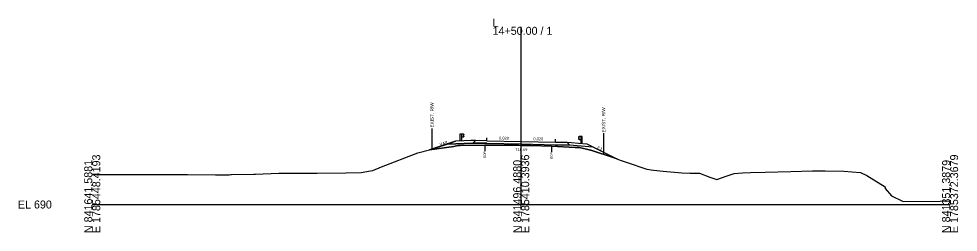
# Model space of a CAD drawing. Extents: x -26 to 5203, y -10 to 9576.
# Drawn here: x -25.7 to 302.8, y 4490.3 to 4565 of the extents above; entities that cross this region are included whole.
import ezdxf

# ---------------------------------------------------------------- set-up
doc = ezdxf.new("R2010")
doc.units = 0
for name, color, linetype in [('Exist Cross Section Cell', 7, 'Continuous'), ('Exist XS Center Line Elevation Label', 7, 'Continuous'), ('Exist XS Ground Line', 7, 'Continuous'), ('Old_Level_10', 7, 'Continuous'), ('Prop XS Earthwork Shape', 7, 'Continuous'), ('Prop XS EOT Tick Mark', 7, 'Continuous'), ('Prop XS Finish Grade', 7, 'Continuous'), ('Prop XS Finish Grade Earthwork', 7, 'Continuous'), ('Prop XS Finish Grade Paved Shoulder', 7, 'Continuous'), ('Prop XS Finish Grade Pavement', 7, 'Continuous'), ('Prop XS Guardrail', 7, 'Continuous'), ('Prop XS Hydro Fill Slope Data', 7, 'Continuous'), ('Prop XS Pvmt Edge Slope', 7, 'Continuous'), ('Prop XS SE Text', 7, 'Continuous'), ('Prop XS Side Slope Text', 7, 'Continuous'), ('Prop XS Subgrade Earthwork', 7, 'Continuous')]:
    doc.layers.add(name, color=color, linetype=linetype)

msp = doc.modelspace()

# ---------------------------------------------------------------- linework, layer by layer
at = {"layer": 'Exist Cross Section Cell'}
for p, q in [((150, 4500), (150, 4562.16)), ((0, 4500), (150, 4500)), ((150, 4500), (300, 4500))]:
    msp.add_line(p, q, dxfattribs=at)
at = {"layer": 'Exist XS Ground Line'}
msp.add_lwpolyline([(0, 4510.46), (3.11, 4510.46), (7.54, 4510.46), (18.23, 4510.45), (31.95, 4510.44), (33.34, 4510.44), (43.12, 4510.43), (47.87, 4510.43), (48.41, 4510.44), (48.74, 4510.44), (56.55, 4510.61), (56.95, 4510.62), (57.13, 4510.63), (65.23, 4510.94), (75.36, 4510.97), (78.69, 4511.01), (88.71, 4511.06), (94.05, 4511.18), (97.35, 4511.79), (98.18, 4511.95), (101.14, 4513.17), (113.91, 4518.04), (117.96, 4519.11), (126.45, 4520.32), (127.84, 4520.6), (128.13, 4520.63), (128.65, 4520.63), (137.27, 4520.71), (144.75, 4520.71), (149.05, 4520.72), (150, 4520.69), (153.52, 4520.59), (160.59, 4520.41), (168.85, 4519.96), (170.4, 4519.9), (174.3, 4518.97), (174.31, 4518.97), (182.89, 4516.16), (184.65, 4515.52), (187.01, 4514.72), (193.98, 4512.41), (196.24, 4512.04), (199.62, 4511.66), (206.13, 4511.13), (208.98, 4510.95), (212.34, 4510.96), (216, 4509.55), (218.45, 4508.75), (221.74, 4509.91), (224.46, 4510.83), (227.43, 4511.07), (230.19, 4511.14), (235.33, 4511.28), (244.3, 4511.53), (251.89, 4511.73), (256.32, 4511.83), (262.83, 4511.7), (268.7, 4511.16), (270.86, 4510.11), (277.3, 4506.15), (277.33, 4505.63), (279.46, 4503.07), (279.78, 4502.93), (283.15, 4501.29), (283.6, 4501.03), (296.55, 4501.19), (300, 4501.3)], dxfattribs=at)
at = {"layer": 'Old_Level_10'}
for p, q in [((118.8, 4526.63), (118.8, 4519.23)), ((178.8, 4524.9), (178.8, 4517.5)), ((137.27, 4520.71), (137.27, 4518.66)), ((160.59, 4520.41), (160.59, 4518.36))]:
    msp.add_line(p, q, dxfattribs=at)
at = {"layer": 'Prop XS Earthwork Shape'}
msp.add_lwpolyline([(137.98, 4521.41), (149.98, 4521.17), (161.98, 4520.93), (166.94, 4520.83), (175.05, 4520.18), (183.63, 4515.89), (182.89, 4516.16), (174.31, 4518.97), (174.3, 4518.97), (170.4, 4519.9), (168.85, 4519.96), (160.59, 4520.41), (153.52, 4520.59), (150, 4520.69), (149.05, 4520.72), (144.75, 4520.71), (137.27, 4520.71), (128.65, 4520.63), (128.13, 4520.63), (127.84, 4520.6), (126.45, 4520.32), (117.96, 4519.11), (124.07, 4521.15), (133.1, 4521.51)], close=True, dxfattribs=at)
at = {"layer": 'Prop XS EOT Tick Mark'}
for p, q in [((138, 4522.33), (138, 4523.33)), ((162, 4521.85), (162, 4522.85))]:
    msp.add_line(p, q, dxfattribs=at)
at = {"layer": 'Prop XS Finish Grade'}
for p, q in [((124.07, 4521.15), (127, 4522.13)), ((130, 4522.25), (127, 4522.13)), ((132.43, 4522.34), (130, 4522.25)), ((134, 4522.41), (132.43, 4522.34)), ((166, 4521.77), (167.57, 4521.64)), ((167.57, 4521.64), (170, 4521.45)), ((170, 4521.45), (173, 4521.21)), ((173, 4521.21), (175.05, 4520.18))]:
    msp.add_line(p, q, dxfattribs=at)
at = {"layer": 'Prop XS Finish Grade Earthwork'}
for p, q in [((124.07, 4521.15), (117.96, 4519.11)), ((175.05, 4520.18), (183.63, 4515.89))]:
    msp.add_line(p, q, dxfattribs=at)
at = {"layer": 'Prop XS Finish Grade Paved Shoulder'}
for p, q in [((138, 4522.33), (134, 4522.41)), ((162, 4521.85), (166, 4521.77))]:
    msp.add_line(p, q, dxfattribs=at)
at = {"layer": 'Prop XS Finish Grade Pavement'}
for p, q in [((138, 4522.33), (150, 4522.09)), ((150, 4522.09), (162, 4521.85))]:
    msp.add_line(p, q, dxfattribs=at)
at = {"layer": 'Prop XS Guardrail'}
for p, q in [((128.68, 4524.69), (129.18, 4524.69)), ((128.68, 4522.19), (128.68, 4524.69)), ((129.18, 4524.69), (129.68, 4524.69)), ((129.18, 4524.69), (129.18, 4522.19)), ((129.68, 4524.69), (129.97, 4524.49)), ((129.97, 4524.37), (129.68, 4524.17)), ((129.68, 4524.17), (129.68, 4524.08)), ((129.68, 4524.08), (129.97, 4523.88)), ((129.97, 4524.49), (130, 4524.43)), ((130, 4524.43), (129.97, 4524.37)), ((129.68, 4523.56), (129.18, 4523.56)), ((129.97, 4523.76), (129.68, 4523.56)), ((129.97, 4523.88), (130, 4523.82)), ((130, 4523.82), (129.97, 4523.76)), ((170.03, 4523.64), (170, 4523.58)), ((170, 4523.58), (170.03, 4523.52)), ((170.03, 4523.03), (170, 4522.97)), ((170, 4522.97), (170.03, 4522.91)), ((170.32, 4523.84), (170.03, 4523.64)), ((170.03, 4523.52), (170.32, 4523.32)), ((170.32, 4523.23), (170.03, 4523.03)), ((170.03, 4522.91), (170.32, 4522.71)), ((170.82, 4523.84), (170.32, 4523.84)), ((170.32, 4523.32), (170.32, 4523.23)), ((170.32, 4522.71), (170.82, 4522.71)), ((171.32, 4523.84), (170.82, 4523.84)), ((170.82, 4523.84), (170.82, 4521.34)), ((171.32, 4521.34), (171.32, 4523.84))]:
    msp.add_line(p, q, dxfattribs=at)
at = {"layer": 'Prop XS Hydro Fill Slope Data'}
for p, q in [((127, 4522.13), (117.96, 4519.11)), ((173, 4521.21), (183.63, 4515.89))]:
    msp.add_line(p, q, dxfattribs=at)
at = {"layer": 'Prop XS Pvmt Edge Slope'}
for p, q in [((134, 4522.41), (133.1, 4521.51)), ((166, 4521.77), (166.94, 4520.83))]:
    msp.add_line(p, q, dxfattribs=at)
at = {"layer": 'Prop XS Subgrade Earthwork'}
for p, q in [((133.1, 4521.51), (124.07, 4521.15)), ((137.98, 4521.41), (133.1, 4521.51)), ((137.98, 4521.41), (149.98, 4521.17)), ((149.98, 4521.17), (161.98, 4520.93)), ((161.98, 4520.93), (166.94, 4520.83)), ((166.94, 4520.83), (175.05, 4520.18))]:
    msp.add_line(p, q, dxfattribs=at)

# ---------------------------------------------------------------- texts
at = {"layer": 'Exist Cross Section Cell'}
for s, p in [('L', (140, 4562.16)), ('14+50.00 / 1', (140, 4559.36)), ('EL 690', (-26, 4498.6))]:
    msp.add_text(s, height=2.8, dxfattribs=at).set_placement(p)
for s, p in [('N 841641.5881', (0, 4490)), ('E 1785448.4193', (2.8, 4490)), ('N 841496.4880', (150, 4490)), ('E 1785410.3936', (152.8, 4490)), ('N 841351.3879', (300, 4490)), ('E 1785372.3679', (302.8, 4490))]:
    msp.add_text(s, height=2.8, rotation=90, dxfattribs=at).set_placement(p)
at = {"layer": 'Exist XS Center Line Elevation Label'}
msp.add_text('710.69', height=1, dxfattribs=at).set_placement((147.95, 4518.69))
at = {"layer": 'Old_Level_10'}
for s, height, p in [('EXIST. R/W', 1.181, (119.39, 4526.93)), ('EXIST. R/W', 1.181, (179.39, 4525.21)), ('EOP', 0.787, (137.66, 4516.26)), ('EOP', 0.787, (160.98, 4515.96))]:
    msp.add_text(s, height=height, rotation=90, dxfattribs=at).set_placement(p)
at = {"layer": 'Prop XS SE Text'}
for p in [(142.25, 4522.74), (154.25, 4522.5)]:
    msp.add_text('0.020', height=1, rotation=358.8542, dxfattribs=at).set_placement(p)
at = {"layer": 'Prop XS Side Slope Text'}
for s, rotation, p in [('VAR.', 18.4706, (121.72, 4520.49)), ('2:1', 333.4349, (176.4, 4519.68))]:
    msp.add_text(s, height=1, rotation=rotation, dxfattribs=at).set_placement(p)

doc.saveas('drawing.dxf')
